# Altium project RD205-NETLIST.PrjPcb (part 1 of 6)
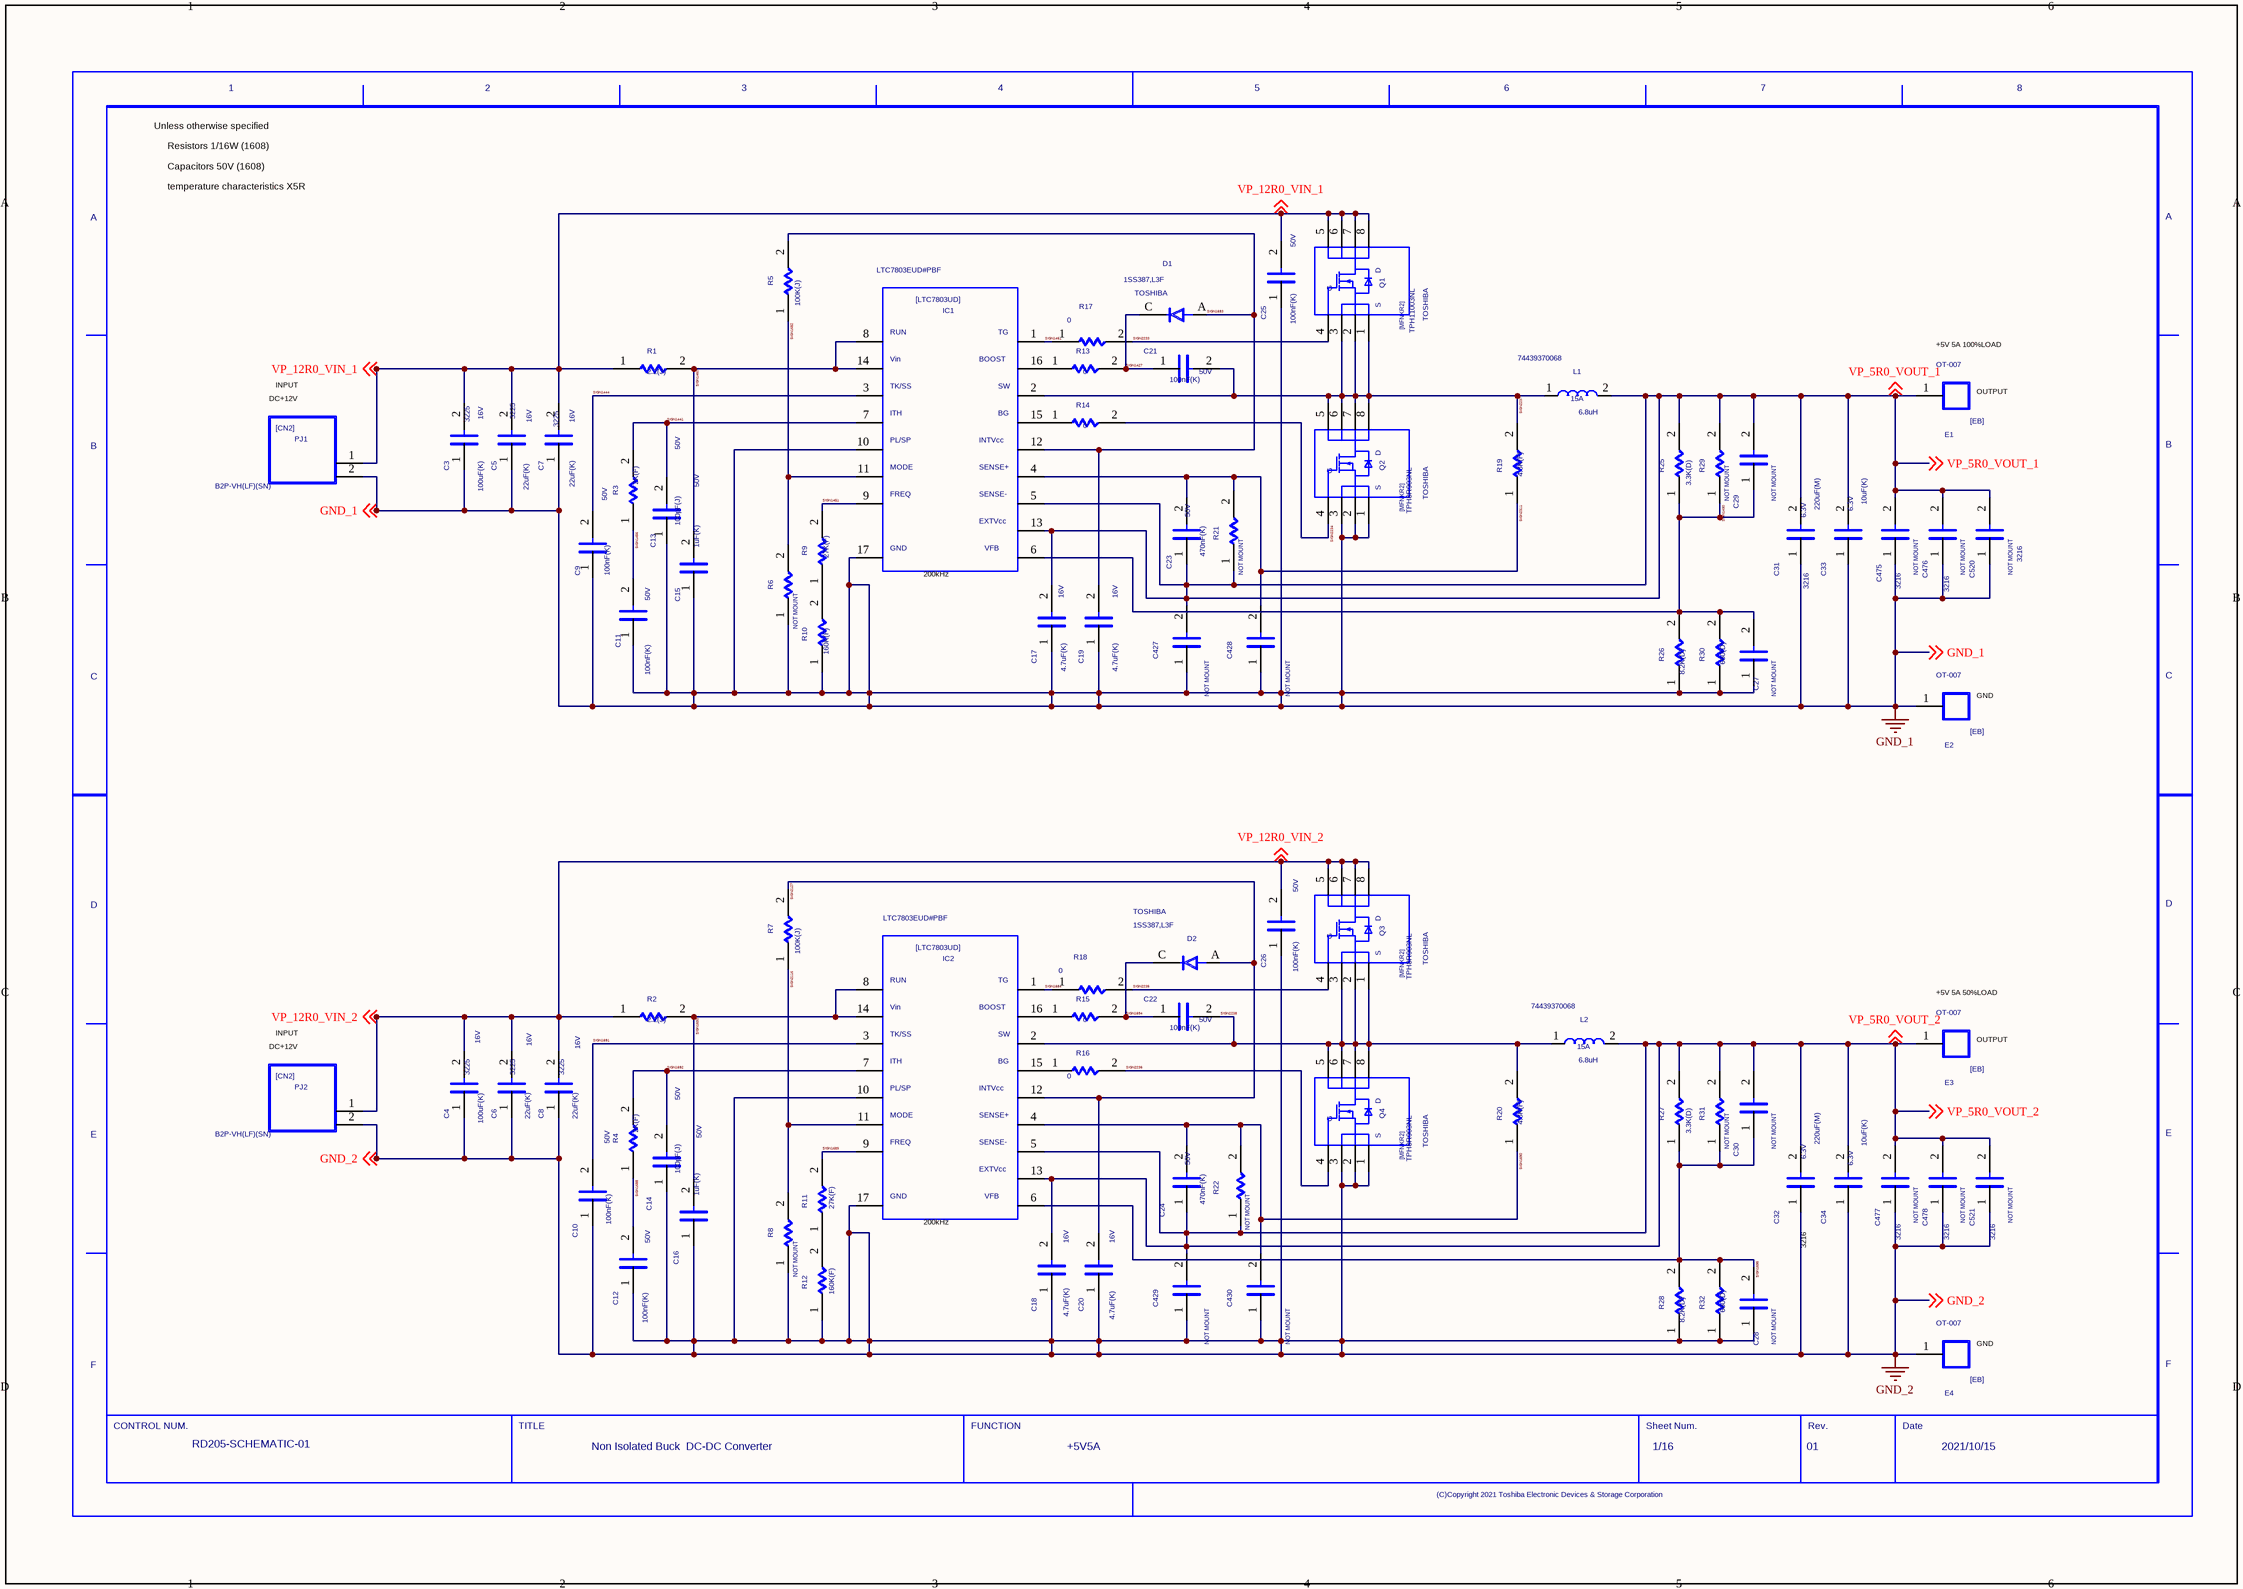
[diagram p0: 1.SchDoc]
16 sheets, 1072 parts. Net scope: global (net labels, ports and power ports of the same name join across sheets).
Sheets:
  1.SchDoc
  2.SchDoc
  3.SchDoc
  4.SchDoc
  5.SchDoc
  6.SchDoc
  7.SchDoc
  8.SchDoc
  9.SchDoc
  10.SchDoc
  11.SchDoc
  12.SchDoc
  13.SchDoc
  14.SchDoc
  15.SchDoc
  16.SchDoc

## Sheet 1.SchDoc
size 420 x 297 mm

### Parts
(Parts that share a designator on the sheet are numbered #1, #2 ... from top to bottom, then left to right.)
C3  SIZECODESMD: 3225  VAL2: 16V  VAL1: 100uF(K)  (hidden comment: C)
C4  SIZECODESMD: 3225  VAL2: 16V  VAL1: 100uF(K)  (hidden comment: C)
C5  SIZECODESMD: 3225  VAL2: 16V  VAL1: 22uF(K)  (hidden comment: C)
C6  SIZECODESMD: 3225  VAL2: 16V  VAL1: 22uF(K)  (hidden comment: C)
C7  SIZECODESMD: 3225  VAL2: 16V  VAL1: 22uF(K)  (hidden comment: C)
C8  SIZECODESMD: 3225  VAL2: 16V  VAL1: 22uF(K)  (hidden comment: C)
C9  VAL2: 50V  VAL1: 100nF(K)  (hidden comment: C)
C10  VAL2: 50V  VAL1: 100nF(K)  (hidden comment: C)
C11  VAL2: 50V  VAL1: 100nF(K)  (hidden comment: C)
C12  VAL2: 50V  VAL1: 100nF(K)  (hidden comment: C)
C13  VAL2: 50V  VAL1: 100pF(J)  (hidden comment: C)
C14  VAL2: 50V  VAL1: 100pF(J)  (hidden comment: C)
C15  VAL2: 50V  VAL1: 1uF(K)  (hidden comment: C)
C16  VAL2: 50V  VAL1: 1uF(K)  (hidden comment: C)
C17  VAL2: 16V  VAL1: 4.7uF(K)  (hidden comment: C)
C18  VAL2: 16V  VAL1: 4.7uF(K)  (hidden comment: C)
C19  VAL2: 16V  VAL1: 4.7uF(K)  (hidden comment: C)
C20  VAL2: 16V  VAL1: 4.7uF(K)  (hidden comment: C)
C21  VAL2: 50V  VAL1: 100nF(K)  (hidden comment: C)
C22  VAL2: 50V  VAL1: 100nF(K)  (hidden comment: C)
C23  VAL2: 50V  VAL1: 470nF(K)  (hidden comment: C)
C24  VAL2: 50V  VAL1: 470nF(K)  (hidden comment: C)
C25  VAL2: 50V  VAL1: 100nF(K)  (hidden comment: C)
C26  VAL2: 50V  VAL1: 100nF(K)  (hidden comment: C)
C27  NOTMOUNT: NOT MOUNT  (hidden comment: C)
C28  NOTMOUNT: NOT MOUNT  (hidden comment: C)
C29  NOTMOUNT: NOT MOUNT  (hidden comment: C)
C30  NOTMOUNT: NOT MOUNT  (hidden comment: C)
C31  SIZECODESMD: 3216  VAL2: 6.3V  VAL1: 220uF(M)  (hidden comment: C)
C32  VAL2: 6.3V  VAL1: 220uF(M)  (hidden comment: C)
C33  VAL2: 6.3V  VAL1: 10uF(K)  (hidden comment: C)
C34  VAL2: 6.3V  VAL1: 10uF(K)  (hidden comment: C)
C427  NOTMOUNT: NOT MOUNT  (hidden comment: C)
C428  NOTMOUNT: NOT MOUNT  (hidden comment: C)
C429  NOTMOUNT: NOT MOUNT  (hidden comment: C)
C430  NOTMOUNT: NOT MOUNT  (hidden comment: C)
C475  NOTMOUNT: NOT MOUNT  SIZECODESMD: 3216  (hidden comment: C)
C476  NOTMOUNT: NOT MOUNT  SIZECODESMD: 3216  (hidden comment: C)
C477  NOTMOUNT: NOT MOUNT  SIZECODESMD: 3216  (hidden comment: C)
C478  NOTMOUNT: NOT MOUNT  SIZECODESMD: 3216  (hidden comment: C)
C520  NOTMOUNT: NOT MOUNT  SIZECODESMD: 3216  (hidden comment: C)
C521  NOTMOUNT: NOT MOUNT  SIZECODESMD: 3216  (hidden comment: C)
D1  USERCOMPTEXT3: TOSHIBA  VAL3: 1SS387,L3F  (hidden comment: D)
D2  COMPCOMMENT: TOSHIBA  VAL3: 1SS387,L3F  (hidden comment: D)
E1  VAL3: OT-007  (hidden comment: EB)
E2  VAL3: OT-007  (hidden comment: EB)
E3  VAL3: OT-007  (hidden comment: EB)
E4  VAL3: OT-007  (hidden comment: EB)
IC1  VAL3: LTC7803EUD#PBF  (hidden comment: LTC7803UD)
IC2  VAL3: LTC7803EUD#PBF  (hidden comment: LTC7803UD)
L1  VAL3: 74439370068  VAL2: 15A  VAL1: 6.8uH  (hidden comment: L)
L2  VAL3: 74439370068  VAL2: 15A  VAL1: 6.8uH  (hidden comment: L)
PJ1  VAL3: B2P-VH(LF)(SN)  (hidden comment: CN2)
PJ2  VAL3: B2P-VH(LF)(SN)  (hidden comment: CN2)
Q1  USERCOMPTEXT3: TOSHIBA  VAL3: TPH11003NL  (hidden comment: MFNKR2)
Q2  USERCOMPTEXT3: TOSHIBA  VAL3: TPH8R903NL  (hidden comment: MFNKR2)
Q3  USERCOMPTEXT3: TOSHIBA  VAL3: TPH8R903NL  (hidden comment: MFNKR2)
Q4  USERCOMPTEXT3: TOSHIBA  VAL3: TPH8R903NL  (hidden comment: MFNKR2)
R1  VAL1: 2.2(J)  (hidden comment: R)
R2  VAL1: 2.2(J)  (hidden comment: R)
R3  VAL1: 2K(F)  (hidden comment: R)
R4  VAL1: 2K(F)  (hidden comment: R)
R5  VAL1: 100K(J)  (hidden comment: R)
R6  NOTMOUNT: NOT MOUNT  (hidden comment: R)
R7  VAL1: 100K(J)  (hidden comment: R)
R8  NOTMOUNT: NOT MOUNT  (hidden comment: R)
R9  VAL1: 27K(F)  (hidden comment: R)
R10  VAL1: 160K(F)  (hidden comment: R)
R11  VAL1: 27K(F)  (hidden comment: R)
R12  VAL1: 160K(F)  (hidden comment: R)
R13  VAL1: 0  (hidden comment: R)
R14  VAL1: 0  (hidden comment: R)
R15  VAL1: 0  (hidden comment: R)
R16  VAL1: 0  (hidden comment: R)
R17  VAL1: 0  (hidden comment: R)
R18  VAL1: 0  (hidden comment: R)
R19  VAL1: 4.3K(F)  (hidden comment: R)
R20  VAL1: 4.3K(F)  (hidden comment: R)
R21  NOTMOUNT: NOT MOUNT  (hidden comment: R)
R22  NOTMOUNT: NOT MOUNT  (hidden comment: R)
R25  VAL1: 3.3K(D)  (hidden comment: R)
R26  VAL1: 8.2K(D)  (hidden comment: R)
R27  VAL1: 3.3K(D)  (hidden comment: R)
R28  VAL1: 8.2K(D)  (hidden comment: R)
R29  NOTMOUNT: NOT MOUNT  (hidden comment: R)
R30  VAL1: 680(D)  (hidden comment: R)
R31  NOTMOUNT: NOT MOUNT  (hidden comment: R)
R32  VAL1: 680(D)  (hidden comment: R)
U?#1  DATE: 2021/10/15  SHEETNUMBER: 1/16  TITLE: Non Isolated Buck / DC-DC Converter  REVISION: 01  DRAWINGNUMBER: RD205-SCHEMATIC-01  FUNCTION: +5V5A  (hidden comment: WAKU_DEF100)

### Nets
GND_1: C3.1 C5.1 C7.1 C9.1 C11.1 C13.1 C15.1 C17.1 C19.1 C25.1 C27.1 C31.1 C33.1 C427.1 C428.1 C475.1 C476.1 C520.1 E2.1 IC1.10 IC1.17 PJ1.2 Q2.1 Q2.2 Q2.3 R6.1 R10.1 R26.1 R30.1 ; off-sheet GND_1
GND_2: C4.1 C6.1 C8.1 C10.1 C12.1 C14.1 C16.1 C18.1 C20.1 C26.1 C28.1 C32.1 C34.1 C429.1 C430.1 C477.1 C478.1 C521.1 E4.1 IC2.10 IC2.17 PJ2.2 Q4.1 Q4.2 Q4.3 R8.1 R12.1 R28.1 R32.1 ; off-sheet GND_2
SIGN1427: C21.1 D1.C R13.2
SIGN1430: C27.2 C29.1 IC1.6 R25.1 R26.2 R29.1 R30.2
SIGN1441: C13.2 IC1.7 R3.2
SIGN1444: C9.2 IC1.3
SIGN1451: IC1.9 R9.2
SIGN1456: C11.2 R3.1
SIGN1460: C15.2 IC1.8 IC1.14 R1.2
SIGN1461: IC1.1 R17.1
SIGN1682: IC1.11 R5.1 R6.2
SIGN1683: C19.2 D1.A IC1.12 R5.2
SIGN1684: IC2.1 R18.1
SIGN1688: C12.2 R4.1
SIGN1689: IC2.9 R11.2
SIGN1690: C24.2 C430.2 IC2.4 R20.1 R22.2
SIGN1691: C10.2 IC2.3
SIGN1692: C14.2 IC2.7 R4.2
SIGN1693: C16.2 IC2.8 IC2.14 R2.2
SIGN1694: C22.1 D2.C R15.2
SIGN1695: C28.2 C30.1 IC2.6 R27.1 R28.2 R31.1 R32.2
SIGN2116: IC2.11 R7.1 R8.2
SIGN2127: C20.2 D2.A IC2.12 R7.2
SIGN2233: Q1.4 R17.2
SIGN2234: Q2.4 R14.2
SIGN2235: Q3.4 R18.2
SIGN2236: Q4.4 R16.2
SIGN2237: C21.2 IC1.2 L1.1 Q1.1 Q1.2 Q1.3 Q2.5 Q2.6 Q2.7 Q2.8 R19.2
SIGN2238: C22.2 IC2.2 L2.1 Q3.1 Q3.2 Q3.3 Q4.5 Q4.6 Q4.7 Q4.8 R20.2
SIGN2311: C23.2 C428.2 IC1.4 R19.1 R21.2
VP_5R0_VOUT_1: C17.2 C23.1 C29.2 C31.2 C33.2 C427.2 C475.2 C476.2 C520.2 E1.1 IC1.5 IC1.13 L1.2 R21.1 R25.2 R29.2 ; off-sheet VP_5R0_VOUT_1
VP_5R0_VOUT_2: C18.2 C24.1 C30.2 C32.2 C34.2 C429.2 C477.2 C478.2 C521.2 E3.1 IC2.5 IC2.13 L2.2 R22.1 R27.2 R31.2 ; off-sheet VP_5R0_VOUT_2
VP_12R0_VIN_1: C3.2 C5.2 C7.2 C25.2 PJ1.1 Q1.5 Q1.6 Q1.7 Q1.8 R1.1 ; off-sheet VP_12R0_VIN_1
VP_12R0_VIN_2: C4.2 C6.2 C8.2 C26.2 PJ2.1 Q3.5 Q3.6 Q3.7 Q3.8 R2.1 ; off-sheet VP_12R0_VIN_2
NetIC1_15: IC1.15 R14.1
NetIC1_16: IC1.16 R13.1
NetIC2_15: IC2.15 R16.1
NetIC2_16: IC2.16 R15.1
NetR9_1: R9.1 R10.2
NetR11_1: R11.1 R12.2

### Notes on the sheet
- Unless otherwise specified
- Capacitors 50V (1608)
- temperature characteristics X5R
- Resistors 1/16W (1608)
- INPUT
- (near E1) +5V 5A 100%LOAD
- (near E1) OUTPUT
- DC+12V
- (near IC1) 200kHz
- (near E2) GND
- (near E3) +5V 5A 50%LOAD
- (near E3) OUTPUT
- (near IC2) 200kHz
- 3216
- (near E4) GND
